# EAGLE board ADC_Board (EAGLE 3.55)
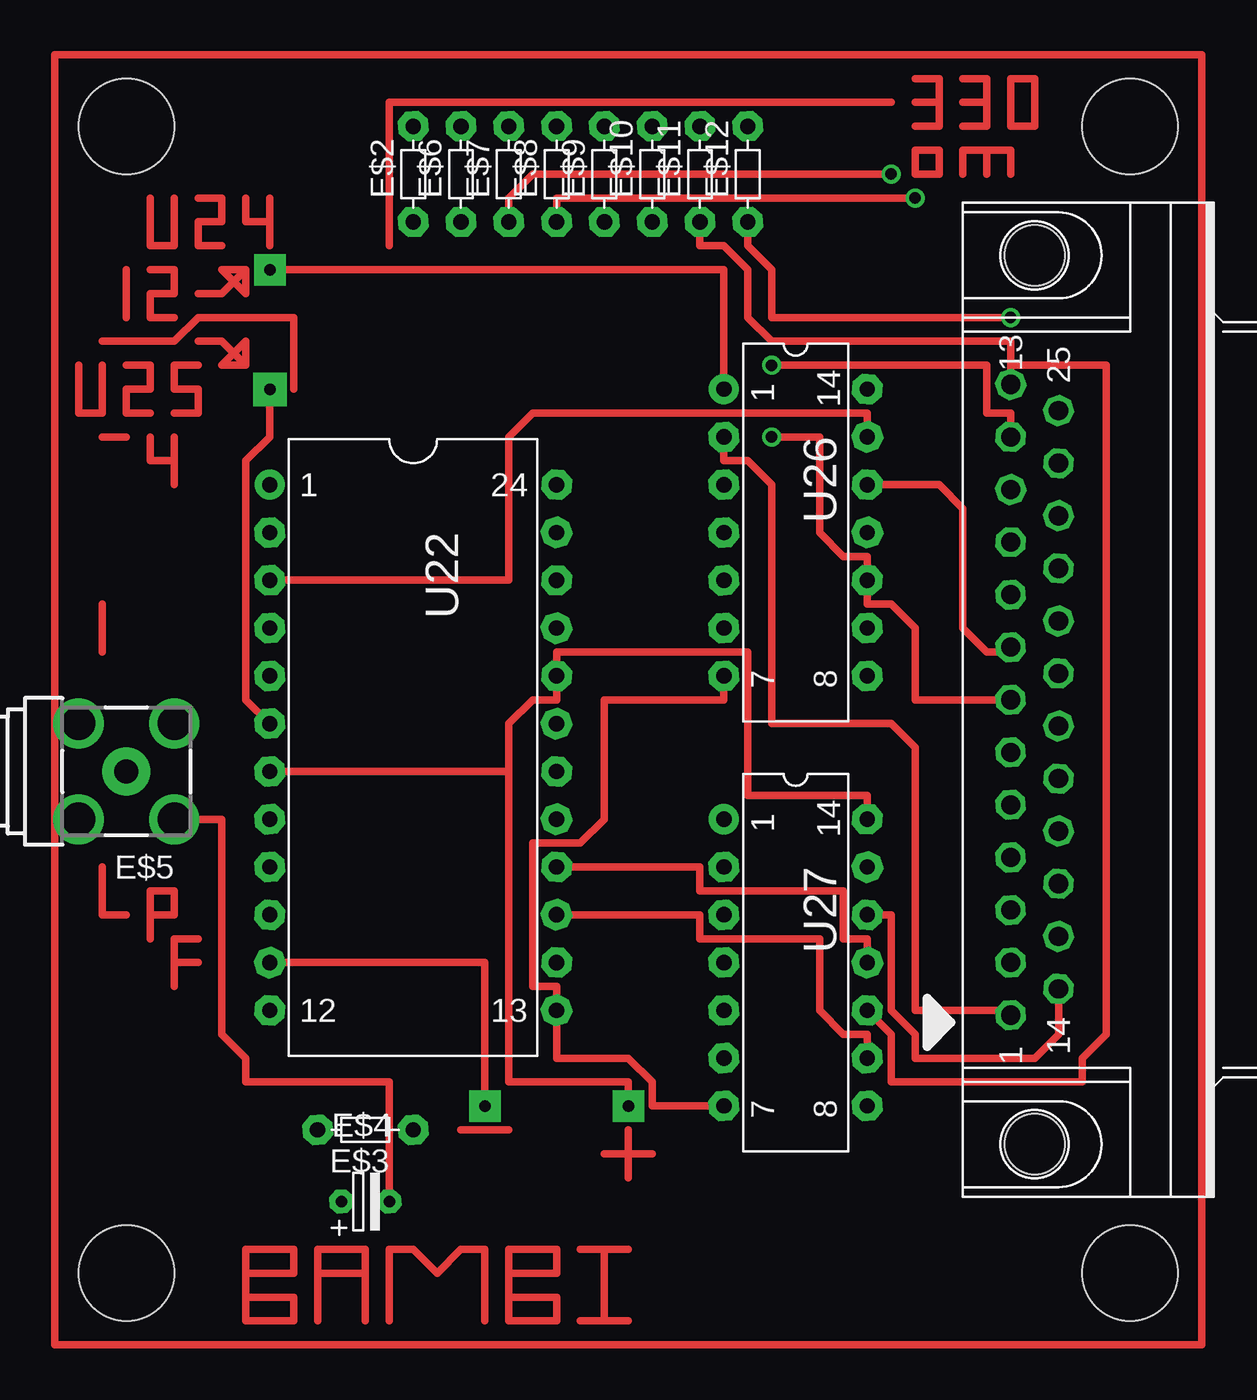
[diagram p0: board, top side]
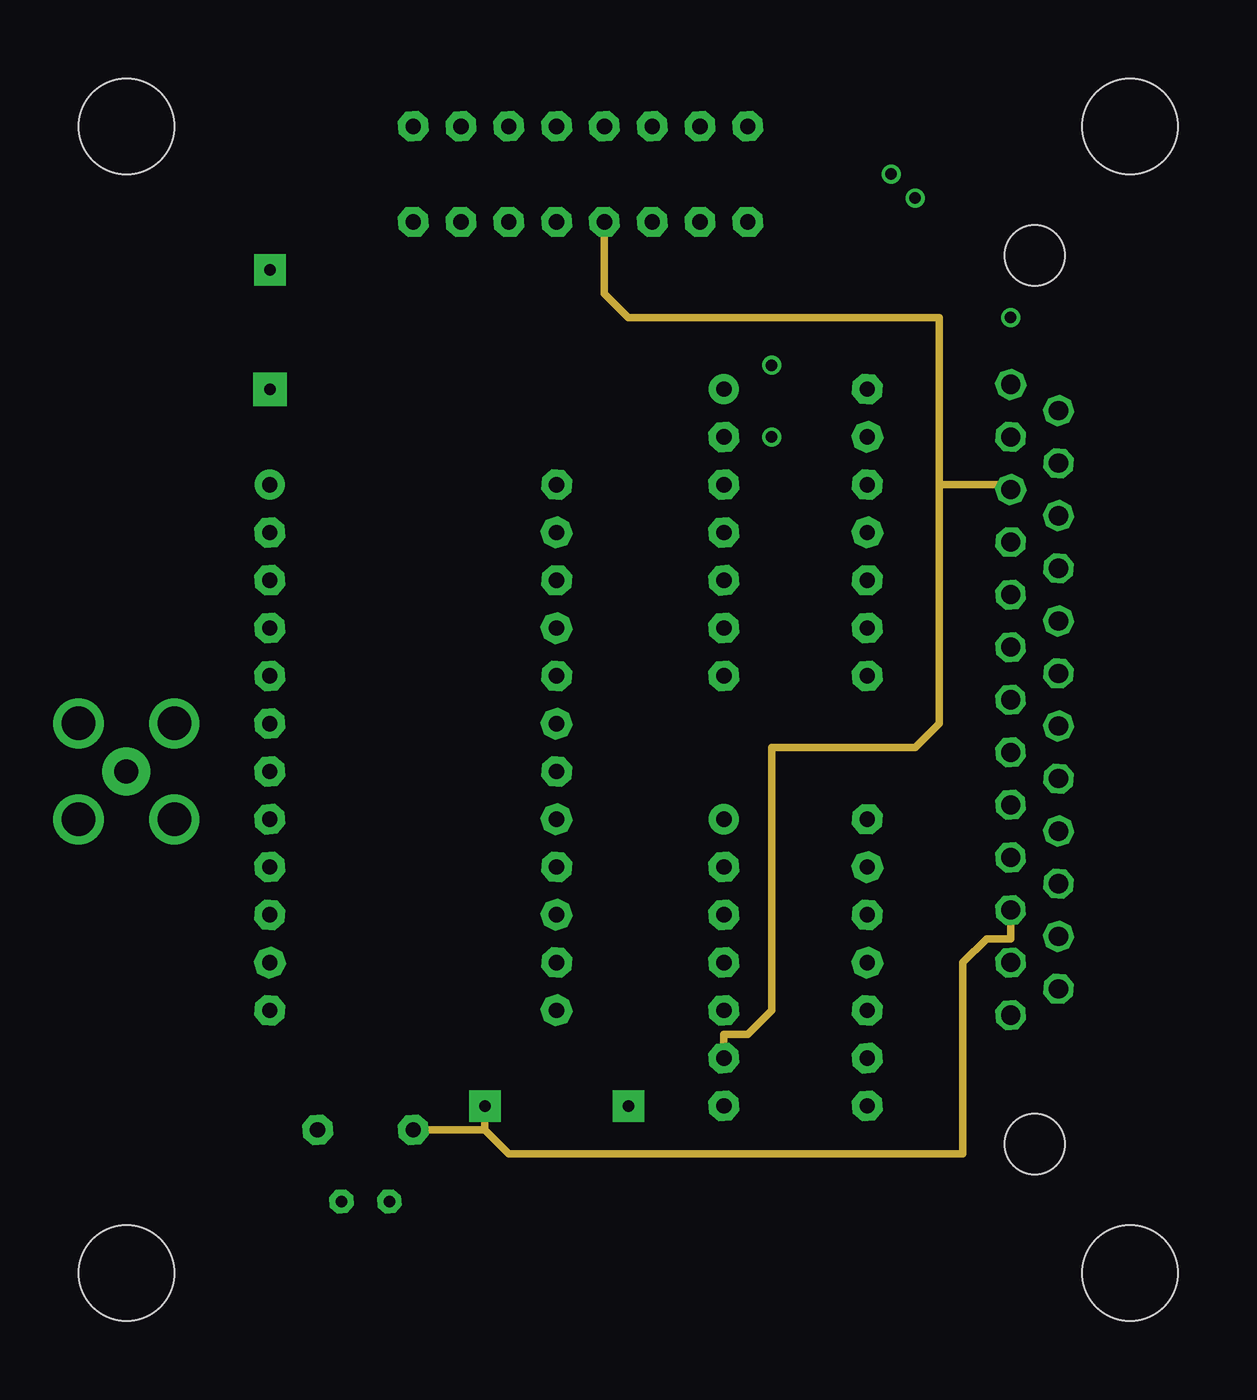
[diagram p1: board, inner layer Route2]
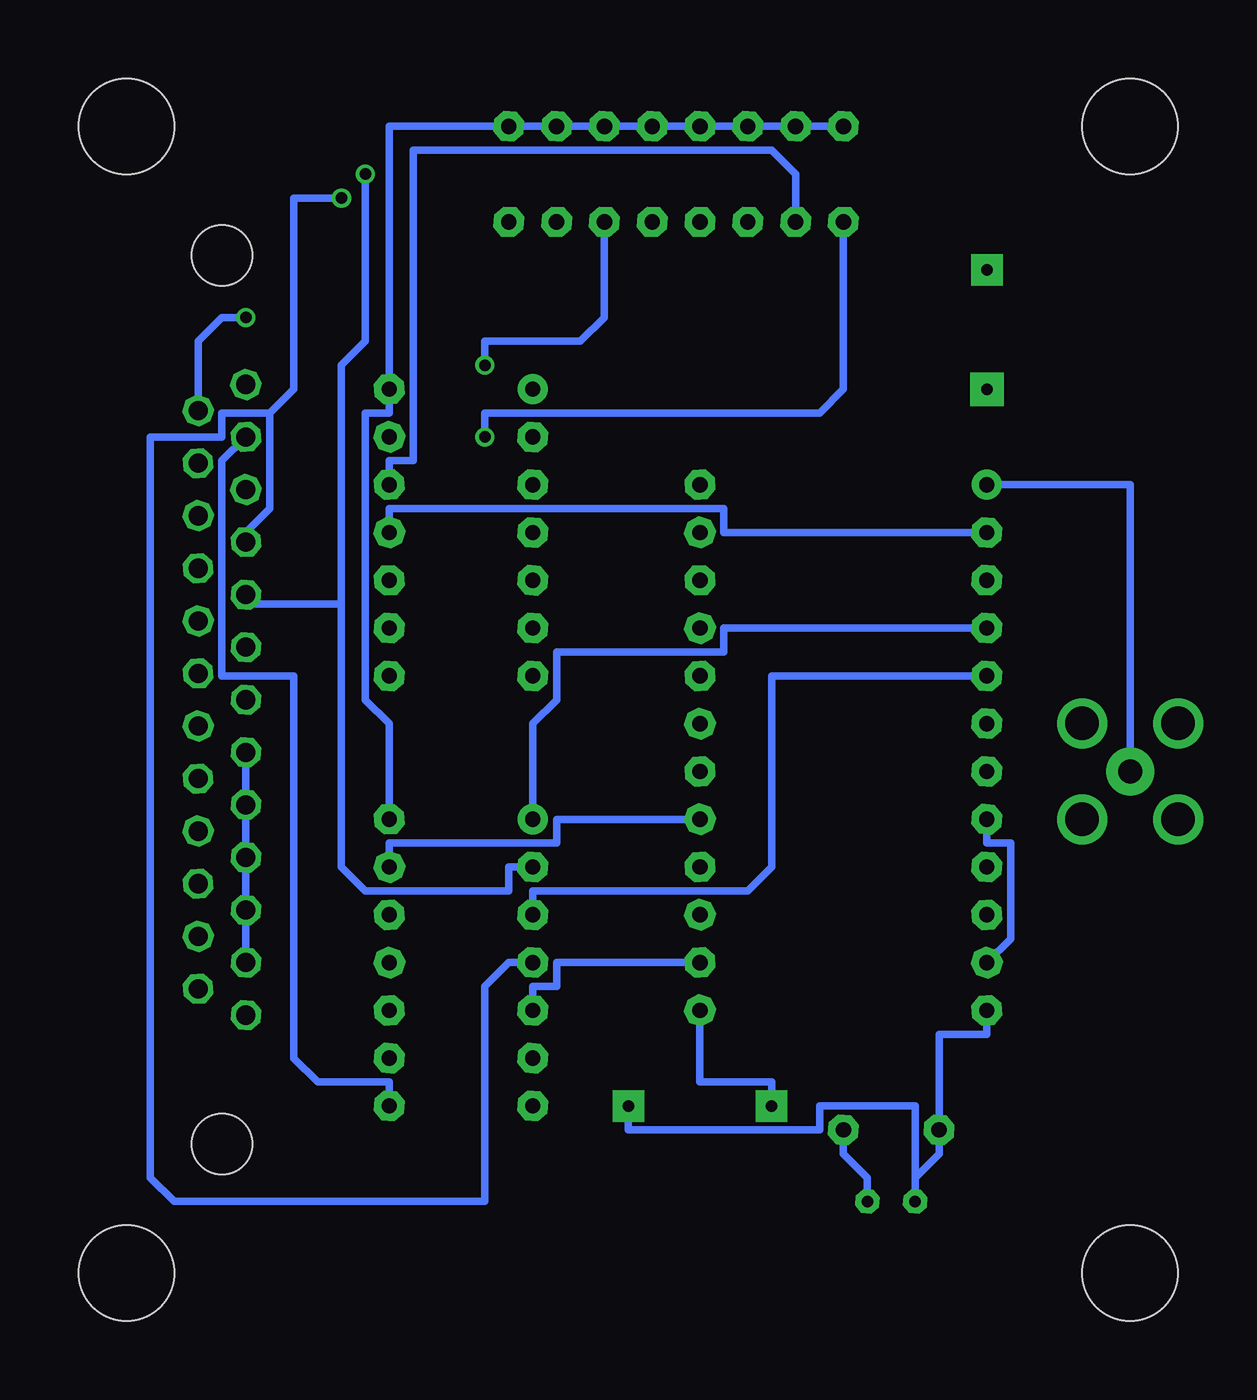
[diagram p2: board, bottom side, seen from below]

No outline drawn. Coordinates in mm, seen from the top.
Copper layers used: Top, Route2, Bottom
Holes 5.08 mm at -2.54,93.98 50.8,93.98 -2.54,33.02 50.8,33.02

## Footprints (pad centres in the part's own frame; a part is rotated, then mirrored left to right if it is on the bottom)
25M/90 = drill 1.016 pad 1.575 octagon:  16.764,-1.27;  13.97,-1.27;  11.176,-1.27;  8.382,-1.27;  5.588,-1.27;  2.794,-1.27;  0,-1.27;  -2.794,-1.27;  -5.588,-1.27;  -8.382,-1.27;  -11.176,-1.27;  -13.97,-1.27;  -16.764,-1.27;  15.367,1.27;  12.573,1.27;  9.779,1.27;  6.985,1.27;  4.191,1.27;  1.397,1.27;  -1.397,1.27;  -4.191,1.27;  -6.985,1.27;  -9.779,1.27;  -12.573,1.27;  -15.367,1.27 | hole 3.2: 23.622,0; -23.622,0
5 = drill 0.813 pad 1.6 octagon:  -2.54,0;  2.54,0
-2,5 = drill 0.61 pad 1.27 octagon:  -1.27,0;  1.27,0
-SMA-G = drill 1.27 pad 2.54 round:  0,0 | drill 1.778 pad 2.54 round:  -2.55,2.55;  2.55,2.55;  2.55,-2.55;  -2.55,-2.55
L24-6 = drill 0.813 pad 1.6 round:  -13.97,-7.62 | drill 0.813 pad 1.6 octagon:  -11.43,-7.62;  -8.89,-7.62;  -6.35,-7.62;  -3.81,-7.62;  -1.27,-7.62;  1.27,-7.62;  3.81,-7.62;  6.35,-7.62;  8.89,-7.62;  11.43,-7.62;  13.97,-7.62;  13.97,7.62;  11.43,7.62;  8.89,7.62;  6.35,7.62;  3.81,7.62;  1.27,7.62;  -1.27,7.62;  -3.81,7.62;  -6.35,7.62;  -8.89,7.62;  -11.43,7.62;  -13.97,7.62
L14 = drill 0.813 pad 1.6 round:  -7.62,-3.81 | drill 0.813 pad 1.6 octagon:  -5.08,-3.81;  -2.54,-3.81;  0,-3.81;  2.54,-3.81;  5.08,-3.81;  7.62,-3.81;  7.62,3.81;  5.08,3.81;  2.54,3.81;  0,3.81;  -2.54,3.81;  -5.08,3.81;  -7.62,3.81

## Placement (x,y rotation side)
E$1  [25M/90]  45.72,63.5 270 top
E$2  [5]  12.7,91.44 90 top
E$3  [5]  10.16,40.64 180 top
E$4  [-2,5]  10.16,36.83 0 top
E$5  [-SMA-G]  -2.54,59.69 180 top
E$6  [5]  15.24,91.44 90 top
E$7  [5]  17.78,91.44 90 top
E$8  [5]  20.32,91.44 90 top
E$9  [5]  22.86,91.44 90 top
E$10  [5]  25.4,91.44 90 top
E$11  [5]  27.94,91.44 90 top
E$12  [5]  30.48,91.44 90 top
U22  ADC0820  [L24-6]  12.7,60.96 270 top
U26  7417  [L14]  33.02,72.39 270 top
U27  7417  [L14]  33.02,49.53 270 top

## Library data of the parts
E$1 = connect
E$2-E$4 E$6-E$12 = discrete
E$5 = con-coax
U22 U26 U27 = 74xx

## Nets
S$1: U22. U26.
S$2: U22. U26.
S$3: U22. U27.
S$4: U22. U27.
S$5: U22. U27.
S$6: U22. U27.
S$7: U22. U27.
S$8: U22. U27.
S$10: E$2. E$3. E$4. U22. U26. U27.
S$13: E$1. U26.
S$14: E$1. E$3. E$4. E$5. U22. U26. U27.
S$15: U26.
S$16: E$1. E$2. U26.
S$17: E$1. E$6. U26.
S$18: E$1. E$7. U27.
S$19: E$1. E$8. U27.
S$20: E$1. E$9. U27.
S$21: E$1. E$10. U27.
S$22: E$1. E$11. U27.
S$23: E$1. U27.
S$26: E$5. U22.
S$34: E$1. E$12.
S$41: U22.

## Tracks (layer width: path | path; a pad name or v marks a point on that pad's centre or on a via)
S$1
  Bottom 0.406: 5.08,72.39 19.05,72.39 19.05,73.66 36.83,73.66 36.83,72.39
S$2
  Top 0.406: 5.08,69.85 17.78,69.85 17.78,77.47 19.05,78.74 36.83,78.74 36.83,77.47
S$3
  Bottom 0.406: 5.08,67.31 19.05,67.31 19.05,66.04 27.94,66.04 27.94,63.5 29.21,62.23 29.21,57.15
S$4
  Bottom 0.406: 5.08,64.77 16.51,64.77 16.51,54.61 17.78,53.34 29.21,53.34 29.21,52.07
S$5
  Bottom 0.406: 20.32,49.53 27.94,49.53 27.94,48.26 29.21,48.26 29.21,46.99
S$6
  Top 0.406: 20.32,52.07 27.94,52.07 27.94,50.8 34.29,50.8 34.29,46.99 35.56,45.72 36.83,45.72 36.83,44.45
S$7
  Top 0.406: 20.32,54.61 27.94,54.61 27.94,53.34 35.56,53.34 35.56,50.8 36.83,50.8 36.83,49.53
S$8
  Bottom 0.406: 20.32,57.15 27.94,57.15 27.94,55.88 36.83,55.88 36.83,54.61
S$9
  Top 0.406: 15.24,40.64 17.78,40.64
S$10  (via drill 0.61 pad 1.68)
  Top 0.406: U27. 36.83,58.42 30.48,58.42 30.48,66.04 20.32,66.04 20.32,64.77 20.32,63.5 19.05,63.5 17.78,62.23 17.78,59.69 | 17.78,59.69 5.08,59.69 | 17.78,59.69 17.78,43.18 24.13,43.18 v24.13,41.91
  Bottom 0.406: U27. 36.83,62.23 38.1,63.5 38.1,78.74 36.83,78.74 U26. 36.83,93.98 E$2. | 5.08,46.99 5.08,45.72 7.62,45.72 E$3. 7.62,39.37 8.89,38.1 | v24.13,41.91 24.13,40.64 13.97,40.64 13.97,41.91 8.89,41.91 8.89,38.1 | 8.89,36.83 8.89,38.1
S$11
  Top 0.406: 24.13,39.37 24.13,38.1 | 24.13,39.37 24.13,40.64 | 24.13,39.37 25.4,39.37 | 22.86,39.37 24.13,39.37
S$12
  Top 0.406: -6.35,29.21 -6.35,97.79 54.61,97.79 54.61,29.21 -6.35,29.21
S$13
  Top 0.406: 29.21,77.47 29.21,76.2 30.48,76.2 31.75,74.93 31.75,62.23 38.1,62.23 39.37,60.96 39.37,46.99 44.45,46.99 44.45,46.74
S$14  (via drill 0.61 pad 1.68)
  Top 0.406: E$4. 11.43,43.18 3.81,43.18 3.81,44.45 2.54,45.72 2.54,57.15 0.01,57.14 | 29.21,64.77 29.21,63.5 22.86,63.5 22.86,57.15 21.59,55.88 19.05,55.88 19.05,48.26 20.32,48.26 20.32,46.99 20.32,44.45 24.13,44.45 25.4,43.18 25.4,41.91 29.21,41.91 | v16.51,41.91 16.51,49.53 5.08,49.53
  Route2 0.406: 44.45,52.32 44.45,50.8 43.18,50.8 41.91,49.53 41.91,39.37 17.78,39.37 16.51,40.64 | 16.51,40.64 v16.51,41.91 | 12.7,40.64 16.51,40.64
  Bottom 0.406: 44.45,60.71 44.45,57.91 44.45,55.12 44.45,52.32 44.45,49.53 | 12.7,40.64 12.7,39.37 11.43,38.1 E$4. | 20.32,46.99 20.32,43.18 16.51,43.18 v16.51,41.91 | 5.08,57.15 5.08,55.88 3.81,55.88 3.81,50.8 5.08,49.53
S$15  (via drill 0.61 pad 1.68)
  Top 0.406: 29.21,80.01 29.21,86.36 v5.08,86.36
S$16  (via drill 0.61 pad 1.02)
  Top 0.406: 44.45,63.5 39.37,63.5 39.37,67.31 38.1,68.58 36.83,68.58 36.83,69.85 36.83,71.12 35.56,71.12 34.29,72.39 34.29,77.47 v31.75,77.47
  Bottom 0.406: 12.7,88.9 12.7,80.01 13.97,78.74 31.75,78.74 v31.75,77.47
S$17
  Top 0.406: 36.83,74.93 40.64,74.93 41.91,73.66 41.91,67.31 43.18,66.04 44.45,66.04 44.45,66.29
  Bottom 0.406: 15.24,88.9 15.24,91.44 16.51,92.71 35.56,92.71 35.56,76.2 36.83,76.2 36.83,74.93
S$18  (via drill 0.61 pad 1.02)
  Top 0.406: 17.78,88.9 17.78,90.17 19.05,91.44 v38.1,91.44
  Bottom 0.406: 39.37,68.58 44.45,68.58 44.45,69.09 | 39.37,68.58 39.37,54.61 38.1,53.34 30.48,53.34 30.48,54.61 29.21,54.61 | v38.1,91.44 38.1,82.55 39.37,81.28 39.37,68.58
S$19  (via drill 0.61 pad 1.02)
  Top 0.406: 20.32,88.9 20.32,90.17 v39.37,90.17
  Bottom 0.406: 43.18,78.74 43.18,73.66 44.45,72.39 44.45,71.88 | 43.18,78.74 45.72,78.74 45.72,77.47 49.53,77.47 49.53,38.1 48.26,36.83 31.75,36.83 31.75,48.26 30.48,49.53 29.21,49.53 | v39.37,90.17 41.91,90.17 41.91,80.01 43.18,78.74
S$20
  Route2 0.406: 40.64,74.93 44.45,74.93 44.45,74.68 | 40.64,74.93 40.64,62.23 39.37,60.96 31.75,60.96 31.75,46.99 30.48,45.72 29.21,45.72 29.21,44.45 | 22.86,88.9 22.86,85.09 24.13,83.82 40.64,83.82 40.64,74.93
S$21  (via drill 0.61 pad 1.02)
  Top 0.406: v31.75,81.28 43.18,81.28 43.18,78.74 44.45,78.74 44.45,77.47
  Bottom 0.406: 44.45,77.47 45.72,76.2 45.72,64.77 41.91,64.77 41.91,44.45 40.64,43.18 36.83,43.18 36.83,41.91 | 25.4,88.9 25.4,83.82 26.67,82.55 31.75,82.55 v31.75,81.28
S$22
  Top 0.406: 44.45,81.28 44.45,80.26 44.45,80.01 | 44.45,81.28 49.53,81.28 49.53,45.72 48.26,44.45 48.26,43.18 38.1,43.18 38.1,45.72 36.83,46.99 | 27.94,88.9 27.94,87.63 29.21,87.63 30.48,86.36 30.48,83.82 31.75,82.55 44.45,82.55 44.45,81.28
S$23
  Top 0.406: 36.83,52.07 38.1,52.07 38.1,46.99 39.37,45.72 39.37,44.45 45.72,44.45 46.99,45.72 46.99,48.13 46.99,48.26
S$24
  Top 0.406: -2.54,52.07 -3.81,52.07 -3.81,54.61
S$25
  Top 0.406: -3.81,66.04 -3.81,68.58
S$26
  Bottom 0.406: 5.08,74.93 -2.54,74.93 -2.54,59.69
S$27
  Top 0.406: -1.27,52.07 -1.27,53.34 0,53.34 0,52.07 -1.27,52.07 | -1.27,50.8 -1.27,52.07
S$28
  Top 0.406: 0,49.53 0,48.26 | 1.27,50.8 0,50.8 0,49.53 | 1.27,49.53 0,49.53
S$29
  Top 0.406: -1.27,90.17 -1.27,87.63 0,87.63 0,90.17
S$30
  Top 0.406: 1.27,90.17 2.54,90.17 2.54,88.9 1.27,88.9 1.27,87.63 2.54,87.63
S$31
  Top 0.406: 3.81,90.17 3.81,88.9 5.08,88.9 | 5.08,88.9 5.08,90.17 | 5.08,88.9 5.08,87.63
S$32
  Top 0.406: -5.08,81.28 -5.08,78.74 -3.81,78.74 -3.81,81.28
S$33
  Top 0.406: -2.54,81.28 -1.27,81.28 -1.27,80.01 -2.54,80.01 -2.54,78.74 -1.27,78.74
S$34  (via drill 0.61 pad 1.02)
  Top 0.406: v44.45,83.82 31.75,83.82 31.75,86.36 30.48,87.63 30.48,88.9
  Bottom 0.406: v44.45,83.82 45.72,83.82 46.99,82.55 E$1. 46.99,78.74
S$35
  Top 0.406: 39.37,96.52 40.64,96.52 40.64,95.25 | 40.64,95.25 39.37,95.25 | 40.64,95.25 40.64,93.98 39.37,93.98
S$36
  Top 0.406: 41.91,96.52 43.18,96.52 43.18,95.25 | 41.91,93.98 43.18,93.98 43.18,95.25 | 41.91,95.25 43.18,95.25
S$37
  Top 0.406: 44.45,93.98 44.45,96.52 45.72,96.52 45.72,93.98 44.45,93.98
S$38
  Top 0.406: 39.37,92.71 39.37,91.44 40.64,91.44 40.64,92.71 39.37,92.71
S$39
  Top 0.406: 41.91,91.44 41.91,92.71 43.18,92.71 | 43.18,92.71 43.18,91.44 | 43.18,92.71 44.45,92.71 44.45,91.44
S$40
  Top 0.406: 38.1,95.25 11.43,95.25 11.43,87.63
S$41  (via drill 0.61 pad 1.78)
  Top 0.406: 5.08,62.23 3.81,63.5 3.81,76.2 5.08,77.47 v5.08,80.01
S$42
  Top 0.406: 1.27,81.28 0,81.28 0,80.01 1.27,80.01 1.27,78.74 0,78.74
S$43
  Top 0.406: -3.81,77.47 -2.54,77.47
S$44
  Top 0.406: -1.27,77.47 -1.27,76.2 0,76.2 | 0,76.2 0,77.47 | 0,76.2 0,74.93
S$45
  Top 0.406: 1.27,82.55 2.54,82.55 3.81,81.28 | 3.81,81.28 3.81,82.55 2.54,81.28 3.81,81.28
S$46
  Top 0.406: -2.54,86.36 -2.54,83.82
S$47
  Top 0.406: -1.27,86.36 0,86.36 0,85.09 -1.27,85.09 -1.27,83.82 0,83.82
S$48
  Top 0.406: 1.27,85.09 2.54,85.09 3.81,86.36 | 3.81,86.36 2.54,86.36 3.81,85.09 3.81,86.36
S$49
  Top 0.406: -3.81,82.55 0,82.55 1.27,83.82 6.35,83.82 6.35,80.01
S$50
  Top 0.406: 3.81,31.75 3.81,30.48 6.35,30.48 6.35,31.75 3.81,31.75 | 3.81,33.02 3.81,34.29 6.35,34.29 6.35,33.02 3.81,33.02 | 3.81,33.02 3.81,31.75
S$51
  Top 0.406: 7.62,30.48 7.62,33.02 | 7.62,33.02 7.62,34.29 10.16,34.29 10.16,33.02 | 10.16,30.48 10.16,33.02 | 10.16,33.02 7.62,33.02
S$52
  Top 0.406: 11.43,30.48 11.43,34.29 12.7,34.29 13.97,33.02 15.24,34.29 16.51,34.29 16.51,30.48
S$53
  Top 0.406: 17.78,31.75 17.78,30.48 20.32,30.48 20.32,31.75 17.78,31.75 | 17.78,33.02 17.78,34.29 20.32,34.29 20.32,33.02 17.78,33.02 | 17.78,33.02 17.78,31.75
S$54
  Top 0.406: 21.59,34.29 22.86,34.29 | 24.13,34.29 22.86,34.29 | 22.86,34.29 22.86,30.48 | 22.86,30.48 21.59,30.48 | 22.86,30.48 24.13,30.48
